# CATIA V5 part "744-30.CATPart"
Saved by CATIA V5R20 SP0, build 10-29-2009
Part number: 744-30
Revision: TUTTO
Definition: NON CONOSCIUTO
Nomenclature: 744-30
Source: Unknown
Bounding box of the stored display mesh (mm): x -28 to 28, y -28.5 to 28, z -30 to 45
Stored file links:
  C:\Users\Utente\Desktop\IO LAVORO\3D X SITO CF\X SITO\744\744-30.CATPart
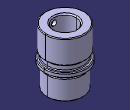
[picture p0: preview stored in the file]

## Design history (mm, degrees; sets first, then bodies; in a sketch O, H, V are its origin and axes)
Body1 "744-30 sol1" (main body)
  Solid1: solid without history
Body2 "IDV1M8_Ingrassatore-1"
  Solid2: solid without history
